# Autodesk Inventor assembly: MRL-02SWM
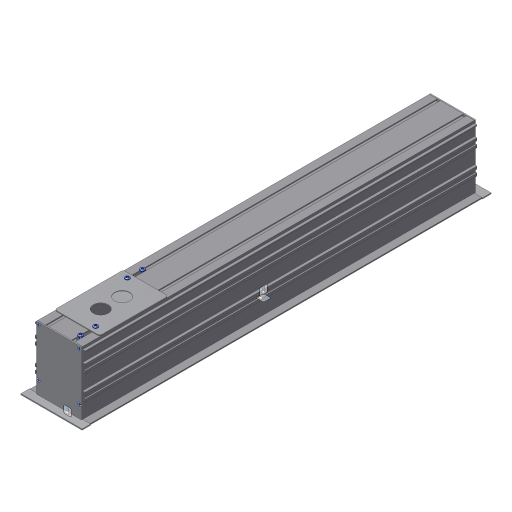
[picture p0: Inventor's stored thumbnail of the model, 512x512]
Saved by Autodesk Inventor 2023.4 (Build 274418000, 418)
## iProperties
Part Number: MRL-02SWM
Document SubType Name: Assembly
Designer: jwb
Project: 22584
Author: jwb
Revision Number: A
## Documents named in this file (15)
- X:\Revit Files\0000-Un-Zipped\LED\MRL-02SWM\MRL-02SWM-2FT.iam
- X:\INVENTOR\845\845035-00-00.ipt
- X:\INVENTOR\725\725760-02288-00.ipt
- 725760-02288.ipt
- X:\INVENTOR\509\509064-00-00.ipt
- X:\INVENTOR\725\725610-02288-00.ipt
- 725610-02288.ipt
- X:\INVENTOR\845\845032-02288-XX.ipt
- X:\INVENTOR\509\509300-00-XX.ipt
- 509300-00-00.ipt
- X:\INVENTOR\850\850013-01-00.iam
- X:\INVENTOR\503\503029-00-00.ipt
- X:\INVENTOR\503\503018-00-00.ipt
- X:\INVENTOR\509\509053-00-00 COILED.ipt
- X:\INVENTOR\501\501018-00-00.ipt
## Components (21 placed, 11 different names)
1. 845032-02288-XX:1
2. 725760-02288:1 — Mate:149, Flush:44, Flush:45, Flush:51
3. 725610-02288:1 — Mate:149, Flush:44, Flush:45
4. 845035-00-00:1 — Mate:124, Flush:36, Mate:125, Insert:98, Insert:99, Insert:100, Insert:101
5. 845035-00-00:2 — Mate:126, Flush:37, Flush:38, Insert:102, Insert:103, Insert:104, Insert:105
6. 850013-01-00:1 [sub-assembly] — Mate:154, Mate:157, Flush:55
7. 850013-01-00:2 [sub-assembly] — Mate:155, Mate:156, Flush:54
8. 509300-00-00:1 — Mate:151, Mate:152, Mate:153, Insert:106, Insert:107
9. 503018-00-00:1 — Insert:101
10. 503018-00-00:2 — Insert:100
11. 503018-00-00:3 — Insert:99
12. 503018-00-00:4 — Insert:98
13. 503018-00-00:5 — Insert:105
14. 503018-00-00:6 — Insert:104
15. 503018-00-00:7 — Insert:103
16. 503018-00-00:8 — Insert:102
17. 509064-00-00:5 — Mate:163, Mate:166, Flush:58, Rigid:1
18. 503029-00-00:1 — Insert:106
19. 503029-00-00:2 — Insert:107
20. 509053-00-00 COILED:1 — Rigid:1
21. 501018-00-00:1
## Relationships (33: Mate 13, Insert 10, Flush 9, WeldJoint 1)
- Mate:124: 845035-00-00:1
- Flush:36: 845035-00-00:1
- Mate:125: 845035-00-00:1
- Mate:126: 845035-00-00:2
- Flush:37: 845035-00-00:2
- Flush:38: 845035-00-00:2
- Insert:98: 845035-00-00:1 ↔ 503018-00-00:4
- Insert:99: 845035-00-00:1 ↔ 503018-00-00:3
- Insert:100: 845035-00-00:1 ↔ 503018-00-00:2
- Insert:101: 845035-00-00:1 ↔ 503018-00-00:1
- Insert:102: 845035-00-00:2 ↔ 503018-00-00:8
- Insert:103: 845035-00-00:2 ↔ 503018-00-00:7
- Insert:104: 845035-00-00:2 ↔ 503018-00-00:6
- Insert:105: 845035-00-00:2 ↔ 503018-00-00:5
- Mate:149: 725760-02288:1 ↔ 725610-02288:1
- Flush:44: 725760-02288:1 ↔ 725610-02288:1
- Flush:45: 725760-02288:1 ↔ 725610-02288:1
- Flush:51: 725760-02288:1
- Mate:151: 509300-00-00:1
- Mate:152: 509300-00-00:1
- Mate:153: 509300-00-00:1
- Mate:154: 850013-01-00:1
- Mate:155: 850013-01-00:2
- Mate:156: 850013-01-00:2
- Flush:54: 850013-01-00:2
- Mate:157: 850013-01-00:1
- Flush:55: 850013-01-00:1
- Mate:163: 509064-00-00:5
- Mate:166: 509064-00-00:5
- Flush:58: 509064-00-00:5
- Insert:106: 509300-00-00:1 ↔ 503029-00-00:1
- Insert:107: 509300-00-00:1 ↔ 503029-00-00:2
- Rigid:1 [WeldJoint]: 509064-00-00:5 ↔ 509053-00-00 COILED:1
